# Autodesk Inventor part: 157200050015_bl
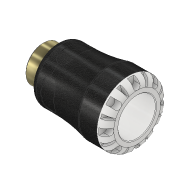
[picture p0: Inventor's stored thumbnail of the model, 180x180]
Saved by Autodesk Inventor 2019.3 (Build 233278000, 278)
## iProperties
Created: 2016-12
Part Number: 157200050015_bl
Material: PVC-Piping
Description: PLASSON  G-PLASS BRASS MALE ADAPTOR 50X 1 1/2" SERIES 1
Document SubType Name: Modeling
Designer: KIM
Mass: 61.7504 g
Surface Area: 140.097 cm^2
Volume: 44.1074 cm^3
Density: 1.4 g/cm^3
Appearance: Black Cast
Author: KIM
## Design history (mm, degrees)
derived "157200.ipt"
feature "Solid1::157200.ipt" dims "ScaleForDerivedMember" = 10
tag "TaggingFeature1"
body "Solid1"
other parameters: "d0" = 126 [user parameter], "d1" = 35.7 [user parameter], "d3" = 62.5 [user parameter], "d4" = 85 [user parameter], "d6" = 85 [user parameter], "d8" = 72.25 [user parameter], "d13" = 9 [user parameter], "d14" = 9 [user parameter], "d15" = 0 [user parameter], "d17" = 360 deg [user parameter], "d19" = 8 deg [user parameter], "d20" = 1 [user parameter], "d21" = 1 [user parameter], "d22" = 8 deg [user parameter], "d24" = 0 [user parameter], "d26" = 360 deg [user parameter], "d32" = 8.5 [user parameter], "d33" = 8.5 [user parameter], "d34" = 47.803 [user parameter], "d38" = 19 [user parameter], "d39" = 1.43409 [user parameter], "d42" = 17.5 [user parameter], "d43" = 11.5 [user parameter], "d45" = 17.64 [user parameter], "d46" = 0 [user parameter], "d59" = 360 deg [user parameter], "d61" = 14.875 [user parameter], "d62" = 1 [user parameter], "d64" = 0 [user parameter], "d65" = 0.85 [user parameter], "d68" = 7.14286 [user parameter], "E_" = 85 [user parameter], "H_" = 126 [user parameter], "l_" = 85 [user parameter], "R_" = 47.803 [user parameter], "l_2" = 19 [user parameter], "d9" = 11.25 [user parameter], "d11" = 85 [user parameter], "d12" = 62.5 [user parameter]
